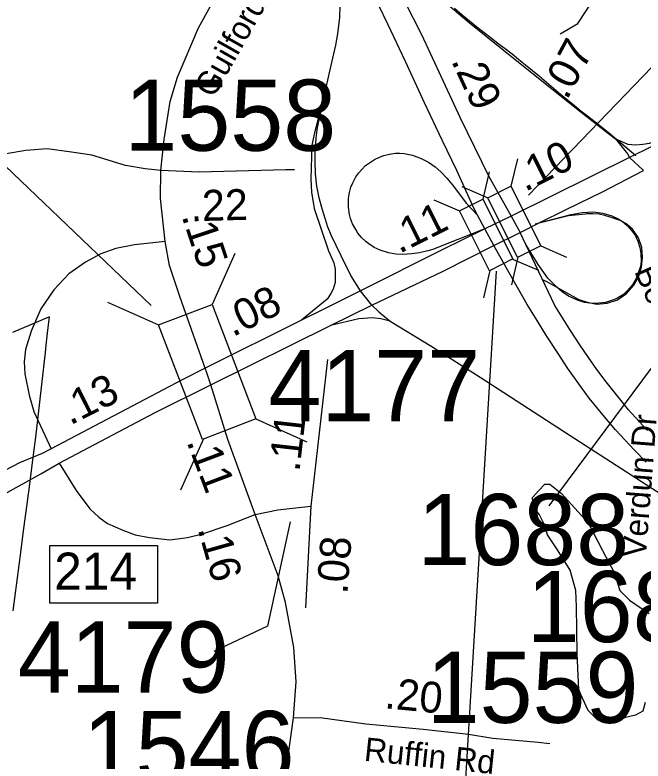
# Model space of a CAD drawing. Extents: x 1662474 to 1856135, y 779280 to 917889.
# Drawn here: x 1727396 to 1729937, y 836306 to 839326 of the extents above; entities that cross this region are included whole.
import ezdxf

# ---------------------------------------------------------------- set-up
doc = ezdxf.new("R2010")
doc.units = 0
for name, color, linetype in [('Cogo Default Point CELL', 7, 'Continuous'), ('Exist Boundary Political City Limit New', 7, 'Continuous'), ('Exist Hydrographic Pond Under 1500 Sq Ft', 7, 'Continuous'), ('Exist Road Non-System Type 51', 7, 'Continuous'), ('Exist Road Non-System Type 51 Label', 7, 'Continuous'), ('Exist Road Primary Interstate Divided Center Attributed', 7, 'Continuous'), ('Exist Road Primary Interstate Interchange CELL', 7, 'Continuous'), ('Exist Road Primary Interstate Mileage Hundredths English Label', 7, 'Continuous'), ('Exist Road Primary Interstate Ramp 1 Lane Attributed', 7, 'Continuous'), ('Exist Road Primary Interstate Structure Standard Bridge CELL', 7, 'Continuous'), ('Exist Road Primary Interstate Structure Standard Bridge Number Label', 7, 'Continuous'), ('Exist Road Secondary Mileage Tenths English Label', 7, 'Continuous'), ('Exist Road Secondary Structure Standard Bridge CELL', 7, 'Continuous'), ('Exist Road Secondary Structure Standard Bridge Number Label', 7, 'Continuous'), ('Exist Road Secondary Type 41 Attributed', 7, 'Continuous'), ('Exist Road Secondary Type 51 Attributed', 7, 'Continuous'), ('Exist Road Secondary Type 51 Divided Attributed', 7, 'Continuous'), ('Exist Road Secondary Type 51 Label', 7, 'Continuous'), ('Exist Road Secondary Type 51 Undivided 4 Lane Attributed', 7, 'Continuous'), ('Map Preparation Boundary City Limit Buffer Line', 7, 'Continuous'), ('Prop DGN Element Guardrail', 7, 'Continuous')]:
    doc.layers.add(name, color=color, linetype=linetype)

msp = doc.modelspace()

# ---------------------------------------------------------------- linework, layer by layer
at = {"layer": 'Cogo Default Point CELL'}
msp.add_line((1730183.9, 838186.1), (1729556.2, 837339.3), dxfattribs=at)
msp.add_lwpolyline([(1728509.5, 837274.3), (1728418.2, 836851.4), (1728200.2, 836749.9)], dxfattribs=at)
at = {"layer": 'Exist Boundary Political City Limit New'}
msp.add_lwpolyline([(1727389.5, 836914), (1727400.2, 836996.5), (1727420.1, 837149.6), (1727430.1, 837226.4), (1727448.2, 837366.1), (1727449.9, 837378.4), (1727454, 837405.8), (1727467.9, 837514.7), (1727480.8, 837616.4), (1727490, 837699.1), (1727504.8, 837830.2), (1727519.4, 837959.4), (1727522.6, 837989.2), (1727528.1, 838037.6), (1727535.5, 838103.5), (1727386.2, 838040.2)], dxfattribs=at)
at = {"layer": 'Exist Hydrographic Pond Under 1500 Sq Ft'}
for points in [[(1729835.4, 836472.6), (1729754.1, 836471.3), (1729714.4, 836511), (1729677, 836592.7), (1729670, 836742.2), (1729667.6, 836931.4), (1729665.3, 836996.8), (1729641.9, 837078.6), (1729590.5, 837160.3), (1729550.8, 837221), (1729536.8, 837265.4), (1729518.1, 837302.8), (1729492.4, 837337.8), (1729490, 837372.9), (1729515.7, 837400.9), (1729539.1, 837426.6), (1729560.1, 837426.6), (1729606.9, 837389.2), (1729714.4, 837270.1), (1729772.8, 837158), (1729819.5, 837069.2), (1729842.9, 836996.8), (1729882.6, 836957.1), (1729934, 836922.1), (1729962.1, 836903.4)], [(1729945.7, 836543.7), (1729936.4, 836508.6), (1729906, 836492.3), (1729866.3, 836482.9), (1729835.4, 836472.6)]]:
    msp.add_lwpolyline(points, dxfattribs=at)
at = {"layer": 'Exist Road Non-System Type 51'}
for points in [[(1729907.5, 838755.2), (1729803.5, 838843.9), (1729762, 838877), (1729712.4, 838916), (1729685.8, 838936.9), (1729658.6, 838958.7), (1729630.8, 838981.1), (1729602.4, 839004.4), (1729574.1, 839028.2), (1729545.9, 839052.5), (1729517.9, 839076.4), (1729490, 839099.8), (1729462, 839122), (1729434.6, 839144.2), (1729432.9, 839145.6), (1729407, 839166.6), (1729379.6, 839188), (1729351.5, 839209.4), (1729322.8, 839231.2), (1729294.1, 839253.6), (1729264.6, 839276.6), (1729234.8, 839300.4), (1729204.9, 839325.5), (1729174.9, 839351.8)], [(1729532.8, 838253.2), (1729548.4, 838245), (1729677.6, 838173.9), (1729710.8, 838162.9), (1729749.8, 838155.4), (1729791.6, 838158.8), (1729832.9, 838173.4), (1729870.4, 838198.2), (1729900.1, 838231.8), (1729919.2, 838268.2), (1729930.1, 838305.9), (1729934.9, 838344.4), (1729932.1, 838384.4), (1729918.8, 838423.9), (1729894.1, 838459.2), (1729876, 838474.9), (1729867.4, 838481.5), (1729853.1, 838489.8), (1729844.5, 838493.4), (1729804.2, 838508), (1729782.6, 838514.7), (1729758.8, 838519.4), (1729734.4, 838521.4), (1729710, 838520.7), (1729703.8, 838520.1), (1729634.8, 838512.4), (1729501.1, 838479.5)]]:
    msp.add_lwpolyline(points, dxfattribs=at)
at = {"layer": 'Exist Road Primary Interstate Divided Center Attributed'}
for points in [[(1728735.6, 839881.4), (1728903.1, 839518.4), (1729041.4, 839247.1), (1729196.9, 838910), (1729311.9, 838675), (1729403.2, 838511.9)], [(1729267.8, 838516), (1729254.4, 838541.5), (1729183.3, 838696.2), (1729124.8, 838818.4), (1729052.4, 838970.5), (1728975.7, 839137.3), (1728904.6, 839289), (1728831.8, 839441.1), (1728764.2, 839587.1), (1728699.4, 839708.7), (1728638.5, 839824.8)], [(1729297.4, 838460), (1729267.8, 838516)], [(1729403.2, 838511.9), (1729440.3, 838445.8)], [(1729333.2, 838392), (1729297.4, 838460)], [(1729463.2, 838397.1), (1729440.3, 838445.8)], [(1729949.8, 837515.7), (1729900.4, 837566.3), (1729825, 837646.6), (1729769.4, 837713.6), (1729719.3, 837775.4), (1729684.1, 837823.8), (1729633.1, 837895.1), (1729593.1, 837955.2), (1729546.5, 838027.7), (1729508, 838088.7), (1729468.3, 838153.9), (1729439.5, 838203.6), (1729394.8, 838281.8), (1729333.2, 838392)], [(1729955.2, 837644.5), (1729920.7, 837679.9), (1729878.1, 837727), (1729841.4, 837773.2), (1729787.1, 837840.7), (1729750, 837890.8), (1729716.1, 837939.2), (1729681.5, 837991), (1729641.1, 838053.2), (1729580, 838149.6), (1729463.2, 838397.1)]]:
    msp.add_lwpolyline(points, dxfattribs=at)
at = {"layer": 'Exist Road Primary Interstate Interchange CELL'}
msp.add_lwpolyline([(1727537.6, 837178), (1727972.5, 837178), (1727972.5, 836944.8), (1727537.6, 836944.8)], close=True, dxfattribs=at)
at = {"layer": 'Exist Road Primary Interstate Ramp 1 Lane Attributed'}
msp.add_line((1728840.2, 838150.5), (1728794.4, 838209.6), dxfattribs=at)
for points in [[(1728735.6, 839881.4), (1728791.4, 839806.6), (1728836.4, 839731.9), (1728881.9, 839663.6), (1728907.4, 839631.2), (1728951.9, 839571.6), (1729023.4, 839488.6), (1729069.7, 839440.2), (1729130.2, 839383.2), (1729234.1, 839294.6), (1729370.8, 839184.9), (1729527, 839059.5), (1729680.2, 838937.3), (1729796.7, 838846.5), (1729825.6, 838824.9)], [(1728649.2, 839007.3), (1728670, 839097.6), (1728685.8, 839168), (1728693.6, 839203.4), (1728701.8, 839248.8), (1728710.2, 839315.8), (1728712.3, 839363.7), (1728713, 839404.3), (1728713, 839435.9), (1728708.5, 839493.4), (1728703.3, 839543.5), (1728693.8, 839595.3), (1728677.6, 839659.7), (1728665.5, 839702.5), (1728654.4, 839738), (1728638.5, 839824.8)], [(1728649.2, 839007.3), (1728608, 838848.7), (1728597.6, 838798.1), (1728592.9, 838660.7), (1728596.3, 838608.5), (1728607.1, 838541.9), (1728664, 838371.7), (1728685.8, 838322), (1728691.4, 838297.4), (1728691.4, 838278.3), (1728691.4, 838243.3), (1728684, 838216.6), (1728674.5, 838198.4), (1728659.4, 838175.9), (1728555.6, 838090.3)], [(1728794.4, 838209.6), (1728754.5, 838270.6), (1728716, 838350.5), (1728675.8, 838435.1), (1728660.9, 838471.1), (1728651.9, 838497.4), (1728638.5, 838541.1), (1728626.8, 838585.6), (1728617.3, 838633.1), (1728611.5, 838683.2), (1728610.2, 838732), (1728610.2, 838764), (1728614.3, 838827.1), (1728619.9, 838870.3), (1728649.2, 839007.3)], [(1729825.6, 838824.9), (1729875.3, 838802.5), (1729907.3, 838800.3), (1729935.8, 838802.5), (1729963.4, 838807.2), (1730051.6, 838831.8)], [(1729825.6, 838824.9), (1729874, 838763.1), (1729881.8, 838748.9)], [(1729297.4, 838460), (1729129.7, 838393.7), (1729087, 838376.9), (1729066.1, 838371.2), (1729032.5, 838362.6), (1729001.8, 838358.3), (1728963.4, 838356.6), (1728936.4, 838358), (1728907, 838363.5), (1728872.9, 838373.7), (1728849.5, 838384.9), (1728827.5, 838398.9), (1728816.9, 838407.4), (1728797.7, 838425.3), (1728783.4, 838443), (1728774.5, 838457.1), (1728762.3, 838480.1), (1728753.6, 838501.3), (1728750, 838517.7), (1728745.2, 838547.5), (1728745.2, 838570), (1728746, 838582.9), (1728749.7, 838607.6), (1728755.3, 838628.3), (1728762.9, 838646), (1728775.4, 838670.7), (1728787.5, 838686.2), (1728798.9, 838700.6), (1728814.8, 838716.9), (1728830.3, 838726.8), (1728850.4, 838740.8), (1728870.5, 838750.6), (1728888.6, 838757.5), (1728911.9, 838762.7), (1728936.2, 838766.2), (1728953, 838765.7), (1728970.9, 838764.8), (1728977.3, 838764), (1729003.8, 838758.8), (1729021.5, 838751.9), (1729039.9, 838745.2), (1729069, 838730.3), (1729095.5, 838710.7), (1729119.2, 838691), (1729142.8, 838665.3), (1729170.4, 838632.7), (1729221.3, 838564.4), (1729267.8, 838516)], [(1729881.8, 838748.9), (1729938, 838697.3), (1729939.1, 838696.1)], [(1729516.2, 838484), (1729646.5, 838518.6), (1729690.6, 838525.9), (1729735.9, 838529.4), (1729774, 838523.3), (1729810.7, 838513), (1729836.6, 838500.9), (1729853.3, 838490.1), (1729872.3, 838473.2), (1729890, 838453.3), (1729904.7, 838433.9), (1729916.3, 838410.6), (1729924.5, 838385.1), (1729928, 838360), (1729929.3, 838328.5), (1729927.1, 838308.2), (1729909.6, 838258.9), (1729894.5, 838233.8), (1729872.9, 838208.8), (1729857.4, 838193.7), (1729831, 838178.1), (1729813.7, 838170.8), (1729784.8, 838161.7), (1729757.5, 838159.1), (1729732.9, 838158.2), (1729700.7, 838161.7), (1729671.3, 838171.2), (1729635.1, 838188), (1729609.1, 838205.8), (1729588, 838223.5), (1729551.2, 838260.6), (1729512.3, 838315.5), (1729463.2, 838397.1)], [(1728004.5, 838408.3), (1727879.7, 838395), (1727804.4, 838381), (1727743, 838358.7), (1727681.7, 838325.3), (1727614.8, 838277.9), (1727553.4, 838213.8), (1727500.5, 838135.8), (1727461.4, 838046.6), (1727439.1, 837971.3), (1727433.5, 837921.2), (1727436.3, 837873.8), (1727453.1, 837787.4), (1727472.6, 837720.5), (1727542.9, 837570.4)], [(1728840.2, 838150.5), (1728867.5, 838124.1), (1728913.7, 838086.5)], [(1728913.7, 838086.5), (1728875.7, 838096), (1728842.4, 838100.3), (1728786.7, 838096), (1728672.6, 838068.4)], [(1728913.7, 838086.5), (1729082.2, 837984.5), (1729277.5, 837860.1), (1729641.8, 837624.2), (1729991.3, 837398.6), (1730234.2, 837247.2), (1730430.3, 837152.8)], [(1727575.2, 837511.5), (1727644.2, 837400.5), (1727699.1, 837326.6), (1727735, 837292.8), (1727770.9, 837267.5), (1727832.2, 837240.1), (1727882.9, 837221.1), (1727939.9, 837210.5), (1728022.3, 837202.1), (1728094.1, 837210.5), (1728155.4, 837225.3), (1728254.6, 837259.1), (1728368, 837303.6)]]:
    msp.add_lwpolyline(points, dxfattribs=at)
at = {"layer": 'Exist Road Primary Interstate Structure Standard Bridge CELL'}
for p, q in [((1729428.6, 838743.5), (1729402.6, 838632.9)), ((1729313.9, 838690.4), (1729288.2, 838579.7)), ((1729204.3, 838631.3), (1729308.4, 838585.8)), ((1729090, 838577.6), (1729194.2, 838532.3)), ((1729523.1, 838390.8), (1729627.2, 838345.2)), ((1729431, 838344.8), (1729405, 838234.1)), ((1729409.4, 838338), (1729513.7, 838292.7)), ((1729317.5, 838291.7), (1729291.8, 838181))]:
    msp.add_line(p, q, dxfattribs=at)
for points in [[(1729402.6, 838632.9), (1729523.5, 838391), (1729429.3, 838343.9), (1729308.4, 838585.8)], [(1729288.2, 838579.7), (1729409.9, 838338.2), (1729315.9, 838290.8), (1729194.2, 838532.3)]]:
    msp.add_lwpolyline(points, close=True, dxfattribs=at)
at = {"layer": 'Exist Road Primary Interstate Structure Standard Bridge Number Label'}
for p, q in [((1729473.4, 838595.9), (1730558.6, 839724.7)), ((1729343.2, 838289.2), (1729191.6, 835782.9))]:
    msp.add_line(p, q, dxfattribs=at)
at = {"layer": 'Exist Road Secondary Structure Standard Bridge CELL'}
for p, q in [((1728286.1, 838360.6), (1728193.8, 838153.9)), ((1727770.9, 838163.4), (1727977.5, 838071.2)), ((1728370, 837690.5), (1728576.7, 837598.2)), ((1728158.6, 837609.6), (1728066.3, 837402.9))]:
    msp.add_line(p, q, dxfattribs=at)
msp.add_lwpolyline([(1728193.8, 838153.9), (1728371, 837690.9), (1728154.7, 837608.1), (1727977.5, 838071.2)], close=True, dxfattribs=at)
at = {"layer": 'Exist Road Secondary Structure Standard Bridge Number Label'}
msp.add_line((1727946.7, 838149.6), (1726165.9, 839850.6), dxfattribs=at)
at = {"layer": 'Exist Road Secondary Type 41 Attributed'}
msp.add_lwpolyline([(1728523.5, 836480.9), (1728631.5, 836482.7), (1728815.5, 836457.1), (1729047.5, 836435), (1729231.4, 836415.4), (1729329.3, 836398.6), (1729513.3, 836383.1), (1729559.4, 836377.1)], dxfattribs=at)
at = {"layer": 'Exist Road Secondary Type 51 Attributed'}
for points in [[(1729601.1, 839249.7), (1729673.7, 839291.1), (1729735.5, 839386.3), (1729819.2, 839540.9)], [(1727985.8, 838696.6), (1727922.7, 838703.1), (1727844.1, 838716.5), (1727707.6, 838757.7), (1727625.3, 838770.9), (1727526.6, 838784.1), (1727440, 838777.5), (1727361.1, 838764.3)], [(1728526.6, 838699.5), (1728492.5, 838698.5), (1728141.4, 838690.1), (1727985.8, 838696.6)], [(1728660.5, 837931), (1728592.7, 837337.3)], [(1728368, 837303.6), (1728460.1, 837322.6), (1728544.3, 837331.9), (1728592.7, 837337.3)], [(1728592.7, 837337.3), (1728571.9, 836926)], [(1728270.7, 835317.7), (1728331.6, 835573), (1728349.6, 835655.1), (1728394.1, 835858.4), (1728454.4, 836107.9), (1728497.2, 836297.7), (1728523.5, 836480.9)]]:
    msp.add_lwpolyline(points, dxfattribs=at)
at = {"layer": 'Exist Road Secondary Type 51 Divided Attributed'}
for points in [[(1730051.6, 838831.8), (1729881.8, 838748.9)], [(1729881.8, 838748.9), (1729569.5, 838593.3), (1729403.2, 838511.9)], [(1729516.2, 838484), (1729626, 838538.5), (1729772.9, 838610.2), (1729939.1, 838696.1)], [(1729403.2, 838511.9), (1729297.4, 838460)], [(1729440.3, 838445.8), (1729516.2, 838484)], [(1729297.4, 838460), (1729122.3, 838374.3), (1728794.4, 838209.6)], [(1729333.2, 838392), (1729440.3, 838445.8)], [(1728840.2, 838150.5), (1729128.2, 838288.7), (1729333.2, 838392)], [(1728794.4, 838209.6), (1728640.2, 838132.5), (1728555.6, 838090.3)], [(1728672.6, 838068.4), (1728840.2, 838150.5)], [(1728555.6, 838090.3), (1728166.3, 837896.4)], [(1728188.2, 837828.1), (1728672.6, 838068.4)], [(1728166.3, 837896.4), (1728072.7, 837848.9), (1727542.9, 837570.4)], [(1727575.2, 837511.5), (1727792.6, 837626.5), (1727963.7, 837717.3), (1728188.2, 837828.1)], [(1727542.9, 837570.4), (1727506.9, 837551.5), (1727414.9, 837512.8), (1727266.1, 837435.8), (1727022.6, 837305.3), (1726525.8, 837048.6), (1725983.5, 836771.9), (1725857.5, 836713.2), (1725638.3, 836603), (1725426.7, 836495.3), (1725218.9, 836394.1)], [(1725250.7, 836321.3), (1725402, 836393.7), (1725558.1, 836474.2), (1725622.6, 836507.1), (1725847, 836630.9), (1725937.7, 836670.3), (1726104.7, 836744), (1726376.8, 836884.8), (1726765.4, 837088), (1727016.1, 837215.1), (1727249.4, 837337.4), (1727352.2, 837386.2), (1727501.1, 837468.4), (1727575.2, 837511.5)]]:
    msp.add_lwpolyline(points, dxfattribs=at)
at = {"layer": 'Exist Road Secondary Type 51 Undivided 4 Lane Attributed'}
for points in [[(1727985.8, 838696.6), (1727999.6, 838821.9), (1728024.6, 838975.9), (1728053.6, 839074.2), (1728138.1, 839273), (1728186.9, 839361.1), (1728239.2, 839446.7), (1728321.1, 839549.5), (1728461.1, 839693.4), (1728542.8, 839758), (1728589.6, 839791.4), (1728638.5, 839824.8)], [(1728004.5, 838408.3), (1727985.4, 838583.4), (1727985.8, 838696.6)], [(1728166.3, 837896.4), (1728062.9, 838186.5), (1728021.2, 838311.6), (1728004.5, 838408.3)], [(1728188.2, 837828.1), (1728172.9, 837877.5), (1728166.3, 837896.4)], [(1728368, 837303.6), (1728256.9, 837607.8), (1728188.2, 837828.1)], [(1728523.5, 836480.9), (1728533.5, 836626.9), (1728524, 836765.2), (1728491.1, 836948.4), (1728460.4, 837056.4), (1728368, 837303.6)]]:
    msp.add_lwpolyline(points, dxfattribs=at)
at = {"layer": 'Map Preparation Boundary City Limit Buffer Line'}
msp.add_lwpolyline([(1727389.5, 836914), (1727400.2, 836996.5), (1727420.1, 837149.6), (1727430.1, 837226.4), (1727448.2, 837366.1), (1727449.9, 837378.4), (1727454, 837405.8), (1727467.9, 837514.7), (1727480.8, 837616.4), (1727490, 837699.1), (1727504.8, 837830.2), (1727519.4, 837959.4), (1727522.6, 837989.2), (1727528.1, 838037.6), (1727535.5, 838103.5), (1727386.2, 838040.2)], dxfattribs=at)

# ---------------------------------------------------------------- texts
at = {"layer": 'Cogo Default Point CELL'}
for s, p in [('1558', (1727838.9, 838776.1)), ('4177', (1728421.3, 837681.5)), ('1688', (1729024.1, 837099.2)), ('1685', (1729466.6, 836787.4)), ('4179', (1727407.4, 836583.2)), ('1559', (1729061.5, 836460.6)), ('1546', (1727670.3, 836220.9))]:
    msp.add_text(s, height=288, dxfattribs=at).set_placement(p)
at = {"layer": 'Exist Road Non-System Type 51 Label'}
msp.add_text('Verdun Dr', height=95, rotation=85.5344, dxfattribs=at).set_placement((1729947.9, 837127.7))
at = {"layer": 'Exist Road Primary Interstate Interchange CELL'}
msp.add_text('214', height=150, dxfattribs=at).set_placement((1727555.1, 836999.7))
at = {"layer": 'Exist Road Primary Interstate Mileage Hundredths English Label'}
msp.add_text('.29', height=125, rotation=294.7751, dxfattribs=at).set_placement((1729159.4, 839140.6))
at = {"layer": 'Exist Road Secondary Mileage Tenths English Label'}
for s, rotation, p in [('.22', 1.5903, (1728107.8, 838490.4)), ('.15', 288.4433, (1728069.5, 838511.6)), ('.13', 26.6891, (1727619.6, 837663.5)), ('.11', 290.6835, (1728089.5, 837599.2)), ('.08', 85.7665, (1728740.9, 836979.6)), ('.20', 354.5586, (1728888.8, 836520.2))]:
    msp.add_text(s, height=125, rotation=rotation, dxfattribs=at).set_placement(p)
at = {"layer": 'Exist Road Secondary Type 51 Label'}
for s, rotation, p in [('Guilford Rd', 60.5455, (1728199.2, 838985.7)), ('Beechdale Rd', 293.5797, (1729900, 838288.4)), ('Ruffin Rd', 354.0798, (1728805.9, 836307.8))]:
    msp.add_text(s, height=95, rotation=rotation, dxfattribs=at).set_placement(p)
at = {"layer": 'Prop DGN Element Guardrail'}
for s, rotation, p in [('.07', 61.596, (1729628.9, 838978.2)), ('.10', 26.4856, (1729459.5, 838608.3)), ('.11', 26.6627, (1728950.7, 838358)), ('.08', 26.4769, (1728277.1, 838021.4)), ('.11', 83.4861, (1728546.8, 837474.4)), ('.16', 285.8545, (1728134.7, 837245.8))]:
    msp.add_text(s, height=125, rotation=rotation, dxfattribs=at).set_placement(p)

doc.saveas('drawing.dxf')
